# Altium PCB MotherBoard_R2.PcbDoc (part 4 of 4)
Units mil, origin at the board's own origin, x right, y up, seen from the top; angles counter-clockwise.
Board outline 9500 x 4600 mil, 4 copper layers (Top Layer, Power Layer, GND Layer, Bottom Layer), stack 61.6 mil thick; 206 components, 289 nets, 935 pads, 328 vias.
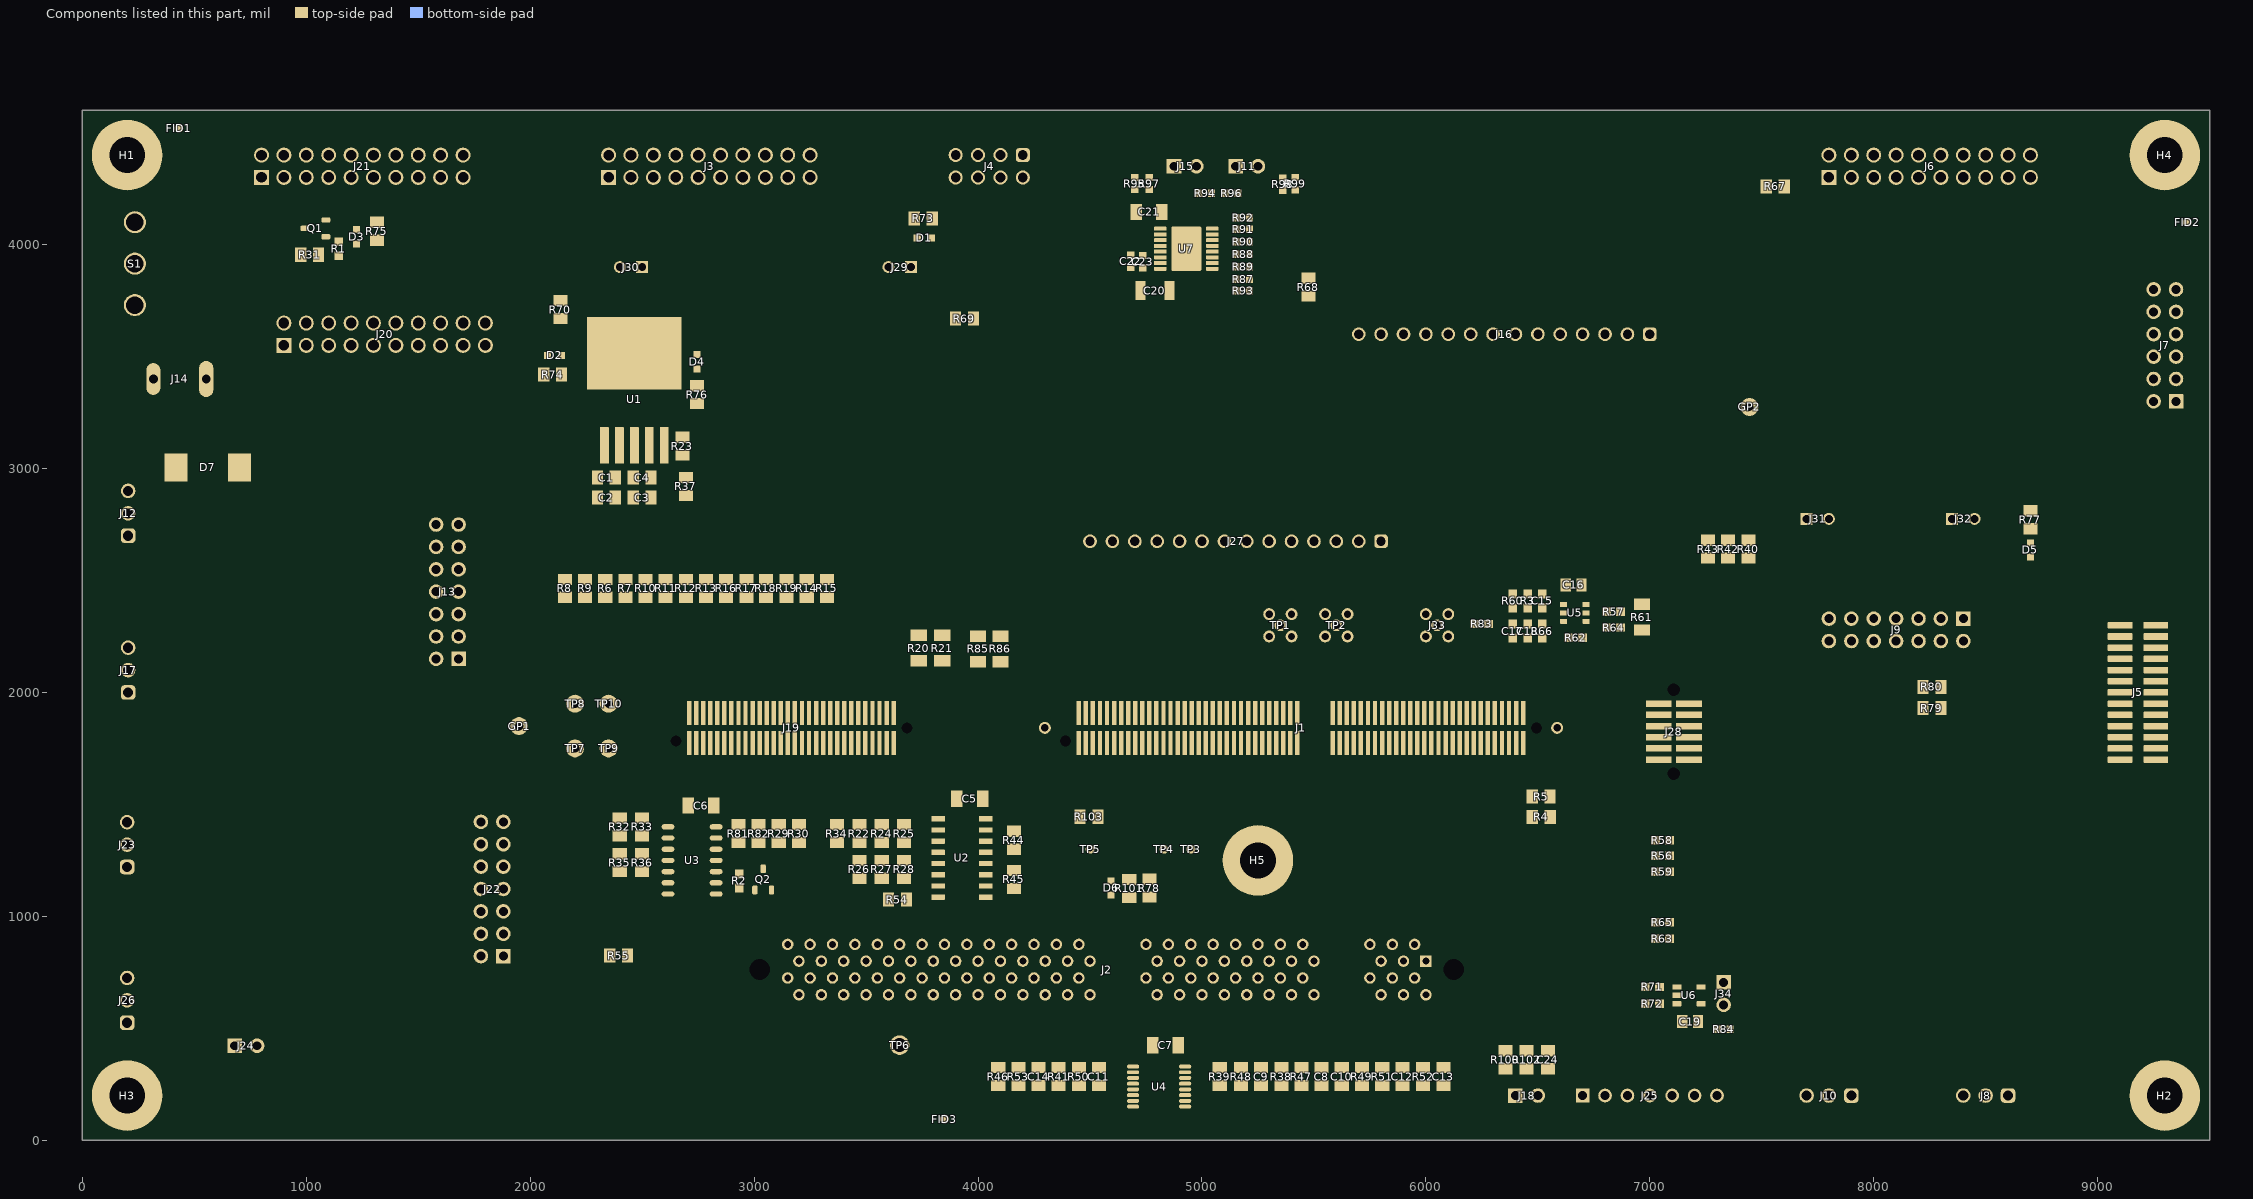
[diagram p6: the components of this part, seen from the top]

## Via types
v1: diameter 28, hole 12, Top Layer to Bottom Layer, 238 vias
v2: diameter 40, hole 20, Top Layer to Bottom Layer, 21 vias
v3: diameter 30, hole 14, Top Layer to Bottom Layer, 19 vias
v4: diameter 28, hole 12, Top Layer to Bottom Layer, tented top, 16 vias
v5: diameter 22, hole 10, Top Layer to Bottom Layer, tented both sides, 12 vias
v6: diameter 60, hole 28, Top Layer to Bottom Layer, 9 vias
v7: diameter 50, hole 28, Top Layer to Bottom Layer, 5 vias
v8: diameter 32, hole 16, Top Layer to Bottom Layer, tented top, 4 vias
v9: diameter 22, hole 10, Top Layer to Bottom Layer, 3 vias
v10: diameter 30, hole 14, Top Layer to Bottom Layer, tented top, 1 vias

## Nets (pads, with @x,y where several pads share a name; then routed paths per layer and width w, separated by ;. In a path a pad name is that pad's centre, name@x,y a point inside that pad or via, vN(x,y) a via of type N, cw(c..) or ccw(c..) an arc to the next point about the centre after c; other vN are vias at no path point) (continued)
pads on no net: FID1.1 FID2.1 FID3.1 H1.1 H4.1 H5.1 J1.32 J1.41 J1.44 J1.66 J1.113 J1.114 J1.115 J1.116 J1.117 J1.181 J1.182 J1.185 J1.186 J2.3 J2.4 J2.5 J2.50 J2.53 J2.54 J2.55 J2.100 J2.MH1 J2.MH2 J3.20 J8.1 J8.2 J8.3 J19.61 J19.62 J19.136 J19.171 J19.172 J19.173 J19.174 J19.175 J19.176 J19.177 J20.8 J20.14 J20.16 J20.18 J21.8 J21.14 J21.16 J21.18 J22.1 J22.3 J28.11 J28.MH1 J28.MH2 S1.1 U7.17@4930,3981.63

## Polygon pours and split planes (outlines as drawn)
VBAT on Power Layer "POWER_LAYER_VBAT_P124" (solid, remove dead copper, pour order 124): 2315.43,3753.33 2733.76,3335 4283.7,3335 4593.7,3645 4635,3686.3 4635,3775 4609.43,3800.57 4134.88,3800.57 4055.18,3720.87 3676.32,3720.87 3635.45,3680 3635.45,3570 3335,3570 3123,3782 2798,3782 2625,3955 2444.67,3774.67 2315.37,3774.67
NetJ14_1 on Power Layer "POWER_LAYER_NETJ14_1_P119" (solid, remove dead copper, pour order 119): 300,3780 300,3680 315,3680 505,3490 604.13,3490 604.13,3594.87 419,3780
GND on Power Layer "POWER_LAYER_GND_P136" (solid, remove dead copper, pour order 136): 2105,4475 2105,4150 2110,4145 2458.43,4145.11 2580.04,4023.49 2580.04,3680 3225,3680 3330,3575 3630,3575 3630,4200 3630,4475
12V on Power Layer "POWER_LAYER_12V_P123" (solid, remove dead copper, pour order 123): 3575,3765 3575,4078.39 3681.61,4185 7210.48,4185 7325,4299.52 7325,4525 7350,4550 8900,4550 9450,4000 9450,3750 9195,3750 9150,3795 9150,4096.92 8746.92,4500 7665.35,4500 7555,4389.65 7555,4200 7175,3820 4125,3820 4040,3735 3604.71,3735
VBAT on Power Layer "POWER_LAYER_VBAT_P121" (solid, remove dead copper, pour order 121): 1425,3789.44 2280.28,3789.44 2315.43,3753.33 2585.56,3750 2625,3789.44 2625,3955 2450,4130 1425,4130
VIN_SMCU on Power Layer "POWER_LAYER_VIN_SMCU_P122" (solid, remove dead copper, pour order 122): 2400,1004.99 2400,545 4615,545 4615,1000.24
VBAT on Power Layer "POWER_LAYER_VBAT_P120" (solid, remove dead copper, pour order 120): 600,50 1390,50 1440,100 1440,4440 1330,4550 600,4550 50,4000 50,600
5V_IPS on Power Layer "POWER_LAYER_5V_IPS_P118" (solid, remove dead copper, pour order 118): 1440,4550 1400,4510 1400,4190 1445,4145 2044.82,4145 2080,4178.98 2080,4300 2250,4470 3380,4470 3650,4200 7200,4200 7300,4300 7300,4525 7275,4550
5V on Power Layer "POWER_LAYER_5V_P125" (solid, remove dead copper, pour order 125): 1450,3785.38 2254.62,3785.37 2725,3315 4296.77,3315 4605.33,3624.1 4660,3676.54 4660,3800 7140,3800 7555,4215 7555,4475 8975,4475 9450,4000 9450,585 8915,50 1500,50 1450,100
GND on GND Layer "GND_LAYER_GND_P117" (solid, remove dead copper, pour order 117): 50,4000 50,600 600,50 8900,50 9450,600 9450,4000 8900,4550 600,4550
no net on Top Layer "TOP_LAYER_NONET_P157" (solid, remove dead copper, pour order 157): 301.94,3780 301.94,3680 330.4,3680 520.4,3490 604.13,3490 604.13,3596.81 420.94,3780
VBAT on Top Layer "TOP_LAYER_VBAT_P155" (solid, remove dead copper, pour order 155): 4190,3675 4143.44,3721.56 4143.44,4143.44 4184,4184 4731.73,4184 4731.73,4115.97 4770,4077.7 4770,3725 4732.57,3675
GND on Top Layer "TOP_LAYER_GND_P153" (solid, remove dead copper, pour order 153): 4874,4071.2 4995,4071.2 4995,4183 4994,4184 4874.56,4184
GND on Top Layer "TOP_LAYER_GND_P151" (solid, remove dead copper, pour order 151): 4870,3752 4993,3752 4993,3890 4994,3891 4882,3891 4882,3824 4870,3812
5V_IPS on Top Layer "TOP_LAYER_5V_IPS_P145" (solid, remove dead copper, pour order 145): 7265,3760 7160,3760 7160,2830 7330,2660 7830,2660 7880,2710 7880,2874.94 7854.94,2900 7785,2900 7760,2875 7760,2731.32 7633.68,2731.32 7565,2800.01 7336.05,2800.01 7265,2871.05
GND on Top Layer "TOP_LAYER_GND_P141" (solid, remove dead copper, pour order 141): 7700,2770 7730,2770 7730,2876.12 7706.12,2900 7397.25,2900 7380,2917.25 7380,3300 7430,3350 7300,3350 7300,2893.25 7372.25,2821 7596.68,2821 7642.68,2775 7700,2775
NetJ14_1 on Top Layer "TOP_LAYER_NETJ14_1_P129" (solid, remove dead copper, pour order 129): 302.25,3780 302.25,3680 330.71,3680 520.71,3490 604.44,3490 604.44,3596.81 421.25,3780
VBAT on Top Layer "TOP_LAYER_VBAT_P140" (solid, remove dead copper, pour order 140): 875.56,3895 830,3849.44 830,2825 1440,2215 1440,3657.97 1572.27,3790.23 2270,3790.23 2310,3750 2584.77,3750 2625,3790.23 2625,3958.37 2453.37,4130 1555,4130 1320,3895
GND on Top Layer "TOP_LAYER_GND_P138" (solid, remove dead copper, pour order 138): 7286,3672.69 7286,3340 9115,3340 9234,3459 9250,3475 9250,3504 9214,3540 7501.33,3540 7333.25,3672.69
5V_IPS on Top Layer "TOP_LAYER_5V_IPS_P139" (solid, remove dead copper, pour order 139): 7160,3760 7160.39,3564 9096,3564 9220,3564 9220,3570 9261,3611 9084,3788 7184.6,3790
EARTH1 on Top Layer "TOP_LAYER_EARTH1_P134" (solid, remove dead copper, pour order 134): 400,50 450,100 450,420 310,560 312.02,562.02 312.02,2897.5 234.52,2975 75,2975 50,2950 50,105 105,50
EARTH on Top Layer "TOP_LAYER_EARTH_P137" (solid, remove dead copper, pour order 137): 7635,240 7660,265 8005,265 8155,115 8742,115 9073,446 9384,446 9450,380 9450,100 9400,50 7685,50 7635,100
VBAT on Top Layer "TOP_LAYER_VBAT_P135" (solid, remove dead copper, pour order 135): 950,4500 900,4550 600,4550 50,4000 50,3020 80,2990 240,2990 330,2900 330,245 525,50 1390,50 1440,100 1440,2250 1150,2540 1150,3400 1150,3770 950,3970
5V_IPS on Top Layer "TOP_LAYER_5V_IPS_P131" (solid, remove dead copper, pour order 131): 1440,4550 1400,4510 1400,4190 1445,4145 2045,4145 2080,4180 2080,4300 2250,4470 3380,4470 3650,4200 7200,4200 7300,4300 7300,4525 7275,4550
3V3 on Top Layer "TOP_LAYER_3V3_P130" (solid, remove dead copper, pour order 130): 2040,3070 1950,2980 1950,2730.02 2000.02,2680 2710,2680 2772.61,2742.61 2772.61,3070
5V_IPS on Bottom Layer "BOTTOM_LAYER_5V_IPS_P127" (solid, remove dead copper, pour order 127): 7063.5,4287.35 7063.5,4180.58 7120.5,4103.37 7120.5,3732.94 7145,3705 7236.42,3705 7250,3718.58 7250,4192.09 7154.75,4287.35
GND on Bottom Layer "BOTTOM_LAYER_GND_P126" (solid, remove dead copper, pour order 126): 7267.85,3708.01 7239.03,3679.84 7239.03,3621.53 7273.48,3588.12 7323.66,3588.12 7395,3659.46 7395,4315.44 7300.44,4410 7185.75,4410 7185.75,4356.33 7267.85,4274.8
GND on Bottom Layer "BOTTOM_LAYER_GND_P133" (solid, remove dead copper, pour order 133): 50,3060 126.8,2983.2 1598.2,2983.2 2080,3465 2080,4065.01 2015.01,4130 1860,4130 1860,4550 600,4550 50,4000
GND on Bottom Layer "BOTTOM_LAYER_GND_P132" (solid, remove dead copper, pour order 132): 1845,4550 1845,4115 2030,4115 2080,4165 2080,4300 2250,4470 3380,4470 3650,4200 7260,4200 7300,4240 7300,4525 7275,4550
3V3 on Bottom Layer "BOTTOM_LAYER_3V3_P128" (solid, remove dead copper, pour order 128): 2255,4450 2100,4295 2100,3460 1450,2810 1450,100 1500,50 8915,50 9450,585 9450,3200 9100,3550 9100,4125 8750,4475 7655,4475 7565,4385 7565,4195 7170,3800 4771.94,3800 4298.42,3320 3615,3320 3560,3375 3560,4120 3632.5,4192.5 3375,4450

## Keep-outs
Keep-Out Layer:
  text ".Layer_Name" at 577,-858.49 h60

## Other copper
Top Layer:
  text ".Layer_Name" at 577,-858.49 h60
GND Layer:
  pour cut-out: 9387.94,3439.94 9413,3465 9413,3565 9388.06,3589.94 9206.38,3589.94 9188,3571.56 9188,3458.33 9206.38,3439.94
  pour cut-out: 9165.82,3647.99 9450,3647.99 9450,3659.28 9170.53,3659.28
  pour cut-out: 9168.06,3653.37
  pour cut-out: 7178.9,3687.01 7275.91,3590 7322.8,3590 7359.14,3626.33 7359.14,3695.86 7244.61,3810.39 7190.39,3810.39 7178.9,3798.9
  pour cut-out: 7650,2850 7625,2825 7625,2725 7650,2700 7850,2700 7875,2725 7875,2825 7850,2850
  pour cut-out: 2061.97,4130 3592.48,4130 3642.48,4180 3641.93,4180.55 3641.93,4190 3630,4190 3585,4145 2061.97,4145
  pour cut-out: 545,3500 565,3500 835,3770 2265,3770 2325,3710 4055,3710 4140,3795 7172.72,3795 7575,4197.28 7575,4385 7650,4460 8775,4460 9050,4185 9050,3793.36 9165.59,3647.45 9170.53,3659.28 9065,3793.02 9065,4190 8780,4475 7639,4475 7555,4391 7555,4209.97 7163.27,3818.24 4123.24,3818.24 4040,3735 2329.31,3735 2271.29,3793.02 828.02,3793.02 545,3510
  pour cut-out: 625,3349.53
  pour cut-out: 895,4115 485,3705 505,3705 900,4100 900,4115
  pour cut-out: 900,4100 2029.37,4100 2100,4165 2100,4294 2256,4450 3372.48,4450 3642.48,4180 7205,4180 7325,4300 7325,4525 7355,4555 7270.01,4555 7299.94,4525 7300,4300 7200,4200 3650.83,4200 3380.83,4470 2250,4470 2080,4300 2080,4180 2015,4115 900,4115
Bottom Layer:
  pour cut-out: 894.99,4114.99 545,3765 545,3500 565,3500 565,3765 900.02,4100.02 2080,4099.98 2080,4115.01
  text ".Layer_Name" at 577,-858.49 h60

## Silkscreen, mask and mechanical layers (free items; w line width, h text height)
Top Overlay:
  lines w10: 29.98,272.3 29.98,1672.3 2029.98,1672.3 2029.98,272.3 375,272.3 ; 500,3150 2200,3150 2200,3800 500,3800 500,3665.04 ; 1925,2720 2875,2720 2875,3675 ; 2100,4500 2100,4200 9100,4200 9100,4500 ; 2155,2550 2165,2550 2200,2585 2205,2585 2240,2550 2250,2550 ; 2512.5,2550 2522.5,2550 2557.5,2585 2562.5,2585 2597.5,2550 2607.5,2550 ; 2872.5,2550 2882.5,2550 2917.5,2585 2922.5,2585 2957.5,2550 2967.5,2550 ; 3232.5,2550 3242.5,2550 3277.5,2585 3282.5,2585 3317.5,2550 3327.5,2550 ; 3390,2680 1925,2680 1925,2200 2985,2200 3400.59,2200 3400.59,2523.07 3402.53,2525 3425,2525 ; 3955,50 3955,565 6150,565 6150,50 ; 4515,3743 4515,4180 ; 5000,195 5000,305 ; 5748.43,3744.03 5748.43,4184.03 ; 6730,800 6730,1085 7335,1085 7335,800 ; 7248.46,4200 7248.97,4200.51 ; 7450,395 6685,395 6685,800 7450,800 ; 8850,1524.7 9050,1525 9050,30 7450,29.7 7450,2529.7 8850,2529.7 8850,1525 ; 9450,1575 8950,1575 8950,4000 9470,4000 ; 29.98,1750 29.98,3150 1830,3150 1829.98,1750 29.98,1750 ; 400,3900 400,4550 2100,4550 2100,3900 400,3900 ; 2100,1675 2100,2165 2105,2170 2490,2170 2490,1675 2100,1675 ; 2225,970 4348.47,970 4348.47,1625 2225,1625 2225,970 ; 2250,3750 3850,3750 3850,4175 2250,4175 2250,3750 ; 3400,2525 3400,3725 7200,3725 7200,2525 3400,2525 ; 6850,1425 6850,2225 7350,2225 7350,1425 6850,1425 ; 7500,2550 8650,2550 8650,2850 7500,2850 7500,2550
  lines w40: 5000,305 5000,310
  text "Fan1" at 4980,4565 h65 r180
  text "Fan2" at 5260,4565 h65 r180
  text "B     R" at 5010,4515 h72.83 r180
  text "B     R" at 5280,4515 h72.83 r180
  text "(5V)" at 5540,4395 h65 r90
  text "(5V)" at 4575,4390 h65 r90
  text "(DRV)" at 5620,4380 h65 r90
  text "(DRV)" at 4655,4375 h65 r90
  text "INVERTER MODULE" at 6010,4342.76 h100
  text "GND /  / 5V (IPS)" at 3575,4265 h72.83
  text "OFF" at 32,4159 h80 r270
  text "INTERMEDIATE" at 1465,4090 h72.83
  text "TRACTION & DC-DC CONTROL MODULE" at 6075,4045 h150
  text "DC-DC GATE DRV POWER SUPPLY" at 2500,4025 h72.83
  text "POWER SUPPLY (IPS)" at 1400,4003.7 h72.83
  text "BLOWER" at 5425,3974.03 h72.83
  text "FAN CTL" at 5435,3929.03 h72.83
  text "VBAT  ->  5V / 5A" at 1490,3925 h60
  text "VBAT  ->  12V" at 2825,3925 h60
  text "'.PRJ_Number'.PCB_Rev" at 6075,3920 h70
  text "VBAT" at 2335,3855 h72.83 r90
  text "GND" at 3690,3790 h72.83
  text "GND" at 2440,3785 h72.83
  text "12V" at 3540,3782 h72.83
  text "ON" at 32,3768 h80 r270
  text "VBAT INPUT" at 620,3602.78 h72.83 r270
  text "READ USER GUIDE BEFORE USE" at 7502,3442.51 h90
  text "CONTROLS POWER SUPPLY" at 1075,3300 h72.83
  text "12V /  / GND /  / 5V_IPS /  / GND /  / 5V /  / GND" at 8965,3240 h65
  text "VBAT  ->  5V / 5A" at 1275,3200 h60
  text "GND" at 7330,3155 h72.83
  text "ANALOG BACK END MODULE" at 4600,3100 h100
  text "POWER SUPPLY" at 1860,3085 h55
  text "5V -> 3V3" at 1865,3010 h60
  text "GND" at 8510.5,2755 h65
  text "GND" at 7515,2750 h65
  text "5V" at 7865,2750 h65
  text "15V" at 8187.5,2750 h65
  text "5V(IPS) ->15V" at 7900,2675 h60
  text "nFLT1H" at 2100,2595 h60
  text "nFLT1L" at 2490,2595 h60
  text "ASCH" at 2855,2595 h60
  text "ASCEN" at 3185,2595 h60
  text "RESOLVER POWER SUPPLY" at 7625,2575 h72.83
  text "nFLT2H" at 2295,2560 h60
  text "nFLT2L" at 2655,2555 h60
  text "ASCL" at 3035,2555 h60
  text "DUAL CAN - 2xTCAN1042" at 302.63,2450 h100
  text "DC-DC CONVERTER  /  / MODULE" at 9181,2354 h90 r90
  text "SEL  SMCU" at 2090,2345 h60 r90
  text "SEL  C2K" at 2010,2340 h60 r90
  text "INV  SAFING" at 1950,2195.02 h65
  text "FAULT CLR" at 4165,2185 h60
  text "DAC-B" at 5245,2150 h72.83
  text "DAC-A" at 5515,2150 h72.83
  text "IDP" at 5986.3,2137.77 h72.83
  text "XBAR TPs" at 2145,2105 h72.83
  text "3V3 SEL" at 8350,2000 h72.83
  text "5V SEL" at 8355,1910 h72.83
  text "SEL  C2K" at 4029,1815 h65 r90
  text "SEL OVP1" at 3807.14,1807.09 h65 r90
  text "SEL OVP2" at 3877.14,1802.09 h65 r90
  text "SEL  SMCU" at 4110,1755 h65 r90
  text "GND" at 1875,1735 h72.83
  text "EXC DAC" at 6124.8,1510 h60
  text "ETAS / EMU" at 6920,1475 h72.83
  text "EXC PWM" at 6120,1425 h60
  text "Io 1" at 6845,1290 h60
  text "DC-DC" at 6650,1240 h60
  text "Io 2" at 6845,1190 h60
  text "VDD" at 4977.8,1155 h60 r90
  text "VDDIO" at 4859.45,1095.5 h60 r90
  text "INVERTER  SAFING" at 2301.77,1055 h60 r90
  text "ERRSTS" at 4535,1055 h60 r90
  text "ASC: DEF / SMCU" at 4330,997.43 h60 r90
  text "ASC: ENDRV" at 3390,986.5 h60
  text "RESOLVER" at 7925,954.7 h100
  text "PWM 6B" at 6758.29,950 h60
  text "TCAN4550" at 779.98,922.3 h100
  text "PWM F" at 7135,915 h60
  text "PWM 7A" at 6758.29,877.96 h60
  text "VBAT TO SMCU" at 2185,730 h55
  text "C2K EN" at 6750,665 h60
  text "SMCU EN" at 6700,585 h60
  text "VOLTAGE MONITOR" at 4500,505 h70
  text "DC DC SAFING" at 6715,418.83 h60
  text "EARTH" at 9188,399 h72.83
  text "ENDRV" at 3555.39,278.39 h60
  text "VREF" at 5420,200 h70 r270
  text "3V3" at 4150,190 h70 r270
  text "15V" at 6011.5,190 h70 r270
  text "VDD" at 4975,185 h70 r270
  text "12V" at 5645,185 h70 r270
  text "5V_I" at 5835.87,185 h70 r270
  text "5V" at 4425,180 h70 r270
  text "VIO" at 5150,180 h70 r270
  text "EARTH" at 366,77 h72.83
  text "Fan Cntl Pot" at 6335,25 h50
  text "QEP / SPI PORT (TEST ONLY)" at 6695.43,25 h50
  text ".Layer_Name" at 577,-858.49 h60
Bottom Overlay:
  text ".Layer_Name" at 577,-858.49 h60
Top Paste:
  text ".Layer_Name" at 577,-858.49 h60
Bottom Paste:
  text ".Layer_Name" at 577,-858.49 h60
Top Solder:
  text ".Layer_Name" at 577,-858.49 h60
  text ".Layer_Name" at 577,-858.49 h60
Bottom Solder:
  text ".Layer_Name" at 577,-858.49 h60
Drill Guide:
  text ".Layer_Name" at 577,-858.49 h60
M1 Board Outline:
  the board outline again, w10
  text ".Layer_Name" at 577,-858.49 h60
M2 Board Dimensions:
  rectangle: 0,-275 125,-150
  rectangle: 125,-400 500,-275
  lines w7: 0,-275 1000,-275 ; 125,-400 125,-150 ; 250,-400 250,-150 ; 500,-400 500,-150 ; 750,-400 750,-150 ; 0,-400 1000,-400 1000,-150 0,-150 0,-400
  text ".Layer_Name" at 577,-858.49 h60
M3 3D STEP Top:
  text ".Layer_Name" at 577,-858.49 h60
M4 3D STEP Bottom:
  text ".Layer_Name" at 577,-858.49 h60
M5 Assembly Top:
  lines w10: -292,-930.17 6308,-930.17 ; -292,-726.83 6310,-726.83 ; -292,-523.5 -292,-1133.5 3713,-1133.5 6310,-1133.5 6310,-523.5 -291.5,-523.5 -291.5,-1133.5 1284,-1133.5 ; 2173,-1133.5 2173,-523.5 ; 3440,-726.83 3440,-523.5 ; 4280,-726.83 4280,-523.5 ; 4902,-1140 4902,-937.17
  text "COMPONENTS MARKED 'DNP' SHOULD NOT BE POPULATED." at 1153.5,-318.5 h60
  text "ASSEMBLY VARIANT:" at 1153,-434 h60
  text ".VariantName" at 2189,-434 h60
  text "PCB VIEWED FROM TOP SIDE" at -228.5,-655.67 h60
  text "BOARD #:" at 2248,-655.67 h60
  text ".PRJ_Number" at 2793.5,-655.67 h60
  text "REV:" at 3638,-655.67 h60
  text ".PCB_Rev" at 3929.5,-655.67 h60
  text "SVN REV:" at 4476,-655.67 h60
  text ".VersionControl_RevNumber" at 4982,-655.67 h60
  text "TID #:" at 2248,-859 h60
  text ".TID" at 2793.5,-859 h60
  text "PLOT NAME =" at -228.5,-1064.34 h60
  text ".plot_File_Name" at 577,-1064.34 h60
  text "GENERATED    :" at 2250,-1064.34 h60
  text ".Print_Date" at 3119.5,-1064.34 h60
  text ".Print_Time" at 3848.5,-1064.34 h60
  text "TEXAS INSTRUMENTS" at 5113,-1064.34 h60
M6 Assembly Bottom:
  lines w10: -292.5,-727.33 6309.5,-727.33 ; -290.5,-930.67 6309.5,-930.67 ; 1115.5,-1140.5 1115.5,-937.67 ; 1737.5,-727.33 1737.5,-524 ; 2577.5,-727.33 2577.5,-524 ; 3844.5,-1134 3844.5,-524 ; 4733.5,-1134 6309,-1134 6309,-524 -292.5,-524 -292.5,-1134 2304.5,-1134 6309.5,-1134 6309.5,-524
  text "COMPONENTS MARKED 'DNP' SHOULD NOT BE POPULATED." at 6102,-318 h60
  text ".VariantName" at 5058,-434 h60
  text "ASSEMBLY VARIANT:" at 6097,-434 h60
  text ".VersionControl_RevNumber" at 1035.5,-656.17 h60
  text "SVN REV:" at 1541.5,-656.17 h60
  text ".PCB_Rev" at 2088,-656.17 h60
  text "REV:" at 2379.5,-656.17 h60
  text ".PRJ_Number" at 3224,-656.17 h60
  text "BOARD #:" at 3769.5,-656.17 h60
  text "PCB VIEWED FROM BOTTOM SIDE" at 6246,-656.17 h60
  text ".TID" at 3224,-859.5 h60
  text "TID #:" at 3769.5,-859.5 h60
  text "TEXAS INSTRUMENTS" at 904.5,-1064.84 h60
  text ".Print_Time" at 2169,-1064.84 h60
  text ".Print_Date" at 2898,-1064.84 h60
  text "GENERATED    :" at 3767.5,-1064.84 h60
  text ".plot_File_Name" at 5440.5,-1064.84 h60
  text "PLOT NAME =" at 6246,-1064.84 h60
M9 Title Sheet:
  drawing of 57 lines, arcs and shapes, not listed
  text "1" at 739.84,8036.5 h70
  text "2" at 3235.5,8036.5 h70
  text "3" at 5724.84,8036.5 h70
  text "4" at 8231.51,8036.5 h70
  text "5" at 10730.5,8036.5 h70
  text "6" at 13235.5,8036.5 h70
  text "A" at -416.5,6893.5 h70
  text "A" at 14383.5,6893.5 h70
  text "B" at -416.5,4513.5 h70
  text "B" at 14383.5,4513.5 h70
  text "C" at -416.5,2138.5 h70
  text "C" at 14383.5,2138.5 h70
  text "PROJECT TITLE:" at 11343.5,277.5 h45
  text ".PRJ_Title" at 11393.5,144.17 h70
  text "DESIGNED FOR:" at 11343.5,-23.5 h45
  text ".PRJ_Customer" at 11393.5,-163.5 h70
  text "D" at -416.5,-231.5 h70
  text "D" at 14383.5,-231.5 h70
  text "FILE NAME:" at 11343.5,-323.5 h45
  text ".PCB_File_Name_No_Path" at 11393.5,-443.5 h70
  text "Texas Instruments (TI) and/or its licensors do not warrant the accuracy or completeness of this specification" at 6374,-605.34 h45
  text "ENGINEER:" at 11343.5,-613.5 h45
  text "LAYOUT BY:" at 12848.5,-613.5 h45
  text "or any information contained therein. TI and/or its licensors do not warrant that this design will meet" at 6329.01,-718 h45
  text ".PRJ_Engineer" at 11393.5,-768.49 h70
  text ".PCB_Layout" at 12899,-768.49 h70
  text "the specifications, will be suitable for your application or fit for any particular purpose, or will operate in" at 6329.01,-830.67 h45
  text ".Layer_Name" at 577,-858.49 h60
  text "ALTIUM DESIGNER VERSION:" at 12848.5,-923.5 h45
  text "an implementation. TI and/or its licensors do not warrant that the design is production worthy. You should" at 6329.01,-943.33 h45
  text "completely validate and test your design implementation to confirm the system functionality for your application." at 6374,-1056 h45
  text ".print_Scale" at 11393.5,-1056.83 h70
  text ".Application_BuildNumber" at 12899,-1056.83 h70
  text "1" at 739.84,-1263.5 h70
  text "2" at 3235.5,-1263.5 h70
  text "3" at 5724.84,-1263.5 h70
  text "4" at 8231.51,-1263.5 h70
  text "5" at 10730.5,-1263.5 h70
  text "6" at 13235.5,-1263.5 h70
M10 Fab Notes:
  drawing of 189 lines, arcs and shapes, not listed
  text "DESIGN INFORMATION" at 12382.02,6356.17 h60
  text "MIN. TRACK WIDTH:" at 11737.46,6224.05 h60
  text "8" at 12833.7,6224.05 h60
  text "MIL" at 12988.46,6224.05 h60
  text "MIN. CLEARANCE:" at 11737.46,6099.92 h60
  text "0.2" at 12773.7,6099.93 h60
  text "mm" at 12988.46,6099.92 h60
  text "MIN. VIA PAD SIZE:" at 11737.46,5975.8 h60
  text "24" at 12803.71,5975.8 h60
  text "MIL" at 12988.46,5975.8 h60
  text "0.05mm (2MIL)" at 12432.46,5845.9 h60
  text "MINIMUM ANNULAR RING" at 11408.23,5837.67 h60
  text "EXTERNAL" at 13140.46,5837.67 h60
  text "PER" at 11608.23,5727.55 h60
  text "IPC-D-275 CLASS 2 LEVEL C" at 11828.23,5727.54 h60
  text "MIL, HOLES" at 13316.46,5627.07 h60
  text "+/-" at 12924,5618.48 h60
  text "+/-" at 13778,5618.48 h60
  text "REGISTRATION TOLERANCES:" at 11408.23,5617.42 h60
  text "METAL" at 12608,5617.42 h60
  text "5" at 13184.2,5617.42 h60
  text "3" at 14017.2,5617.42 h60
  text "MIL" at 14133.46,5617.42 h60
  text "HOLE SIZE TOLERANCE (UNLESS OTHERWISE SPECIFIED):" at 11408.23,5519.1 h60
  text "+/-" at 13778,5516.23 h60
  text "3" at 14017.2,5515.17 h60
  text "MIL" at 14133.46,5515.17 h60
  text "MATERIAL:" at 11333.46,5377.52 h60
  text "FR-4 High Tg" at 12319.9,5249 h60
  text "X" at 12175.46,5241.01 h60
  text "FR-408" at 11754.46,5236.49 h60
  text "OTHER" at 13242.46,5236.49 h60
  text "62 MIL (1.6mm) +/-10%" at 12074.56,5093.46 h60
  text "X" at 11954.46,5091.01 h60
  text "THICKNESS:" at 11408.23,5085.24 h60
  text "OTHER" at 13359.46,5085.24 h60
  text "TOLERANCE:" at 11408.23,4946.92 h60
  text "X" at 12256.46,4946.92 h60
  text "ANSI IPC-6012 TYPE 3 CLASS 2" at 12434.48,4946.92 h60
  text "OTHER +/-" at 12434.46,4802.73 h60
  text "BOW & TWIST:" at 11408.23,4657.54 h60
  text "X" at 12256.46,4657.54 h60
  text "ANSI IPC-6012 TYPE 3 CLASS 2" at 12434.48,4657.54 h60
  text "OTHER +/-" at 12434.46,4510.85 h60
  text "DRILLING:" at 11333.46,4380.23 h60
  text "NC_DRILL FILES" at 13094.46,4275.04 h60
  text "REFERENCE:" at 11408.23,4271.1 h60
  text "X" at 12065.46,4271.01 h60
  text "AS SHOWN" at 12243.46,4271.1 h60
  text "X" at 12966.46,4271.1 h60
  text "OTHER" at 13392.46,4128.85 h60
  text "PTH COPPER THICKNESS:" at 11407.91,4125.32 h60
  text "X" at 12547.14,4125.32 h60
  text "20-30 um" at 12675.14,4125.32 h60
  text "BOARD FINISH:" at 11333.46,3977.73 h60
  text "SILKSCREEN:" at 11488.68,3867.6 h60
  text "X" at 12446.46,3867.6 h60
  text "TOP" at 12563.46,3867.6 h60
  text "X" at 12956.46,3867.6 h60
  text "BOTTOM" at 13074.46,3867.6 h60
  text "SILKSCREEN COLOR:" at 11488.68,3712.41 h60
  text "X" at 12445.46,3712.41 h60
  text "WHITE" at 12563.46,3712.41 h60
  text "OTHER" at 13074.46,3712.41 h60
  text "X" at 12576.46,3568.96 h60
  text "GREEN" at 12694.46,3568.96 h60
  text "OTHER" at 13312.46,3568.96 h60
  text "SOLDER RESIST COLOR:" at 11488.68,3562.1 h60
  text "X" at 12576.46,3414.71 h60
  text "MATTE" at 12694.46,3414.71 h60
  text "SEMI-GLOSS" at 13312,3414.07 h60
  text "IMMERSION GOLD (ENIG)" at 12394.46,3241.94 h60
  text "ENEPIG" at 13732,3234.72 h60
  text "SURFACE FINISH:" at 11333.46,3233.72 h60
  text "HASL LEAD FREE" at 13443.44,3101.4 h60
  text "X" at 12930,3100 h60
  text "IMM. TIN/SILVER OR EQUIV" at 11663,3096.4 h60
  text "OTHER" at 13094.46,3092.47 h60
  text "ARRAY/PANEL:" at 11333.46,2937.09 h60
  text "CUT AND TRIM PER M1 BOARD OUTLINE" at 12394.46,2928.87 h60
  text "N.C. ROUTE" at 12394.46,2792.9 h60
  text "X" at 13082.46,2792.9 h60
  text "V. SCORE" at 13260.46,2792.9 h60
  text "CERTIFICATION:" at 11333.46,2663.77 h60
  text "MATERIALS AND WORKMANSHIP FOR ALL PCBS" at 12058.46,2663.77 h60
  text "TO MEET OR EXCEED THE REQUIREMENTS OF:" at 12058.46,2569.71 h60
  text "X" at 11695.97,2441.08 h60
  text "ANSI IPC-A-600F CLASS ->" at 11823.96,2441.08 h60
  text "X" at 13471.97,2441.08 h60
  text "2" at 13581.96,2441.08 h60
  text "1" at 13266.96,2439.58 h60
  text "3" at 13935.96,2439.58 h60
  text "X" at 12507.97,2293.39 h60
  text "RoHS" at 12635.96,2293.39 h60
  text "OTHER" at 13280.36,2293.39 h60
  text "PER ORDER" at 13677.42,2293.39 h60
  text "ALL BOARDS MUST MEET OR EXCEED UL94-V0 REQUIREMENTS." at 11361,2139.57 h60
  text "PCB MUST BEAR THE UL94V-0 UL REGISTERED MATERIAL ID NUMBER" at 11361,2023.5 h60
  text "ADDITIONAL REQUIREMENTS:" at 11333.46,1854.08 h60
  text "MICROSECTION:" at 11408.23,1746.95 h60
  text "YES" at 12313.96,1746.95 h60
  text "REQUIRED" at 13175.46,1602.62 h60
  text "BARE BOARD ELEC. TEST:" at 11408.23,1599.76 h60
  text "NONE" at 12713.96,1599.76 h60
  text "X" at 13057.46,1599.76 h60
  text "PER ORDER" at 13767.46,1599.76 h60
  text "XX MIL VIAS REQUIRE NON-CONDUCTIVE FILL AND PLANARIZE" at 11576.38,1394.82 h59
  text "XX MIL VIAS REQUIRE CONDUCTIVE FILL AND PLANARIZE" at 11584.38,1290.84 h60
  text "OUTER XX MIL TRACES REQUIRE 50 OHM SINGLE-ENDED IMPEDANCE" at 11583.39,1127.46 h58
  text "LAYER 2 & 3 (INNER LAYERS) XX MIL WIDE, XX MIL SPACE / TRACES REQUIRE 100 OHM DIFFERENTIAL IMPEDANCE" at 11575.39,891.74 h60
  text ".Layer_Name" at 577,-858.49 h60
M11 Gerber Information:
  lines w10: -292,-930.17 6308,-930.17 ; -292,-726.83 6310,-726.83 ; -292,-523.5 -292,-1133.5 3713,-1133.5 6310,-1133.5 6310,-523.5 -291.5,-523.5 -291.5,-1133.5 1284,-1133.5 ; 2173,-1133.5 2173,-523.5 ; 3440,-726.83 3440,-523.5 ; 4280,-726.83 4280,-523.5 ; 4902,-1140 4902,-937.17
  text "ALL ARTWORK VIEWED FROM TOP SIDE" at -228.5,-655.67 h60
  text "BOARD #:" at 2248,-655.67 h60
  text ".PRJ_Number" at 2793.5,-655.67 h60
  text "REV:" at 3638,-655.67 h60
  text ".PCB_Rev" at 3929.5,-655.67 h60
  text "SVN REV:" at 4476,-655.67 h60
  text ".VersionControl_RevNumber" at 4982,-655.67 h60
  text "LAYER NAME =" at -228.5,-858.49 h60
  text "TID #:" at 2248,-859 h60
  text ".TID" at 2793.5,-859 h60
  text "PLOT NAME =" at -228.5,-1064.34 h60
  text ".plot_File_Name" at 577,-1064.34 h60
  text "GENERATED    :" at 2250,-1064.34 h60
  text ".Print_Date" at 3119.5,-1064.34 h60
  text ".Print_Time" at 3848.5,-1064.34 h60
  text "TEXAS INSTRUMENTS" at 5113,-1064.34 h60
M12 Stackup:
  drawing of 295 lines, arcs and shapes, not listed
  text "Layer" at 620.88,6515 h60
  text "Name" at 1030.79,6515 h60
  text "Material" at 1960.54,6515 h60
  text "Thickness" at 2820.3,6515 h60
  text "Constant" at 3470.14,6515 h60
  text "Board Layer Stack" at 4040,6515 h60
  text "1" at 620.88,6395 h60
  text "Top Overlay" at 1030.79,6395 h60
  text "2" at 620.88,6275 h60
  text "Top Solder" at 1030.79,6275 h60
  text "Solder Resist" at 1960.54,6275 h60
  text "0.40mil" at 2820.3,6275 h60
  text "3.5" at 3470.14,6275 h60
  text "3" at 620.88,6155 h60
  text "Top Layer" at 1030.79,6155 h60
  text "Copper" at 1960.54,6155 h60
  text "1.40mil" at 2820.3,6155 h60
  text "4" at 620.88,6035 h60
  text "Dielectric 1" at 1030.79,6035 h60
  text "FR-4" at 1960.54,6035 h60
  text "8.00mil" at 2820.3,6035 h60
  text "4.2" at 3470.14,6035 h60
  text "5" at 620.88,5915 h60
  text "Power Layer" at 1030.79,5915 h60
  text "Copper" at 1960.54,5915 h60
  text "1.40mil" at 2820.3,5915 h60
  text "6" at 620.88,5795 h60
  text "Dielectric 2" at 1030.79,5795 h60
  text "FR-4" at 1960.54,5795 h60
  text "40.00mil" at 2820.3,5795 h60
  text "4.2" at 3470.14,5795 h60
  text "7" at 620.88,5675 h60
  text "GND Layer" at 1030.79,5675 h60
  text "Copper" at 1960.54,5675 h60
  text "1.40mil" at 2820.3,5675 h60
  text "8" at 620.88,5555 h60
  text "Dielectric 3" at 1030.79,5555 h60
  text "FR-4" at 1960.54,5555 h60
  text "8.00mil" at 2820.3,5555 h60
  text "4.2" at 3470.14,5555 h60
  text "9" at 620.88,5435 h60
  text "Bottom Layer" at 1030.79,5435 h60
  text "Copper" at 1960.54,5435 h60
  text "1.40mil" at 2820.3,5435 h60
  text "10" at 620.88,5315 h60
  text "Bottom Solder" at 1030.79,5315 h60
  text "Solder Resist" at 1960.54,5315 h60
  text "0.40mil" at 2820.3,5315 h60
  text "3.5" at 3470.14,5315 h60
  text "11" at 620.88,5195 h60
  text "Bottom Overlay" at 1030.79,5195 h60
  text ".Layer_Name" at 577,-858.49 h60
M13 Component Bodies Top:
  text ".Layer_Name" at 577,-858.49 h60
M14 Component Bodies Bottom:
  text ".Layer_Name" at 577,-858.49 h60
M15 Courtyards Top:
  text ".Layer_Name" at 577,-858.49 h60
M16 Courtyards Bottom:
  text ".Layer_Name" at 577,-858.49 h60
Drill Drawing:
  drawing of 184 lines, arcs and shapes, not listed
  text "Symbol" at 7090.87,11788.02 h72
  text "Quantity" at 7391.44,11788.02 h72
  text "Finished Hole Size" at 7723.44,11788.02 h72
  text "Plated" at 8360,11788.02 h72
  text "Hole Type" at 8619.14,11788.02 h72
  text "Drill Layer Pair" at 8994.3,11788.02 h72
  text "Hole Tolerance" at 9718.63,11788.02 h72
  text "4" at 7391.44,11663.7 h60
  text "50.00mil (1.270mm)" at 7723.44,11663.7 h60
  text "NPTH" at 8360,11663.7 h60
  text "Round" at 8619.14,11663.7 h60
  text "Top Layer - Bottom Layer" at 8994.3,11663.7 h60
  text "2" at 7391.44,11539.38 h60
  text "55.91mil (1.420mm)" at 7723.44,11539.38 h60
  text "NPTH" at 8360,11539.38 h60
  text "Round" at 8619.14,11539.38 h60
  text "Top Layer - Bottom Layer" at 8994.3,11539.38 h60
  text "2" at 7391.44,11415.06 h60
  text "92.91mil (2.360mm)" at 7723.44,11415.06 h60
  text "NPTH" at 8360,11415.06 h60
  text "Round" at 8619.14,11415.06 h60
  text "Top Layer - Bottom Layer" at 8994.3,11415.06 h60
  text "15" at 7391.44,11290.74 h60
  text "10.00mil (0.254mm)" at 7723.44,11290.74 h60
  text "PTH" at 8360,11290.74 h60
  text "Round" at 8619.14,11290.74 h60
  text "Top Layer - Bottom Layer" at 8994.3,11290.74 h60
  text "K" at 7065.58,11280.75 h55.25
  text "254" at 7391.44,11166.42 h60
  text "12.00mil (0.305mm)" at 7723.44,11166.42 h60
  text "PTH" at 8360,11166.42 h60
  text "Round" at 8619.14,11166.42 h60
  text "Top Layer - Bottom Layer" at 8994.3,11166.42 h60
  text "B" at 7065.58,11156.43 h55.25
  text "20" at 7391.44,11042.1 h60
  text "14.00mil (0.356mm)" at 7723.44,11042.1 h60
  text "PTH" at 8360,11042.1 h60
  text "Round" at 8619.14,11042.1 h60
  text "Top Layer - Bottom Layer" at 8994.3,11042.1 h60
  text "F" at 7065.58,11032.11 h55.25
  text "4" at 7391.44,10917.78 h60
  text "16.00mil (0.406mm)" at 7723.44,10917.78 h60
  text "PTH" at 8360,10917.78 h60
  text "Round" at 8619.14,10917.78 h60
  text "Top Layer - Bottom Layer" at 8994.3,10917.78 h60
  text "G" at 7065.58,10907.79 h55.25
  text "24" at 7391.44,10793.46 h60
  text "20.00mil (0.508mm)" at 7723.44,10793.46 h60
  text "PTH" at 8360,10793.46 h60
  text "Round" at 8619.14,10793.46 h60
  text "Top Layer - Bottom Layer" at 8994.3,10793.46 h60
  text "C" at 7065.58,10783.47 h55.25
  text "14" at 7391.44,10669.14 h60
  text "28.00mil (0.711mm)" at 7723.44,10669.14 h60
  text "PTH" at 8360,10669.14 h60
  text "Round" at 8619.14,10669.14 h60
  text "Top Layer - Bottom Layer" at 8994.3,10669.14 h60
  text "D" at 7065.58,10659.15 h55.25
  text "100" at 7391.44,10544.82 h60
  text "31.00mil (0.787mm)" at 7723.44,10544.82 h60
  text "PTH" at 8360,10544.82 h60
  text "Round" at 8619.14,10544.82 h60
  text "Top Layer - Bottom Layer" at 8994.3,10544.82 h60
  text "2" at 7391.44,10420.5 h60
  text "33.07mil (0.840mm)" at 7723.44,10420.5 h60
  text "PTH" at 8360,10420.5 h60
  text "Round" at 8619.14,10420.5 h60
  text "Top Layer - Bottom Layer" at 8994.3,10420.5 h60
  text "15" at 7391.44,10296.18 h60
  text "33.07mil (0.840mm)" at 7723.44,10296.18 h60
  text "PTH" at 8360,10296.18 h60
  text "Round" at 8619.14,10296.18 h60
  text "Top Layer - Bottom Layer" at 8994.3,10296.18 h60
  text "J" at 7065.58,10286.19 h55.25
  text "8" at 7391.44,10171.86 h60
  text "35.04mil (0.890mm)" at 7723.44,10171.86 h60
  text "PTH" at 8360,10171.86 h60
  text "Round" at 8619.14,10171.86 h60
  text "Top Layer - Bottom Layer" at 8994.3,10171.86 h60
  text "6" at 7391.44,10047.54 h60
  text "37.99mil (0.965mm)" at 7723.44,10047.54 h60
  text "PTH" at 8360,10047.54 h60
  text "Round" at 8619.14,10047.54 h60
  text "Top Layer - Bottom Layer" at 8994.3,10047.54 h60
  text "A" at 7065.58,10037.55 h55.25
  text "64" at 7391.44,9923.22 h60
  text "40.00mil (1.016mm)" at 7723.44,9923.22 h60
  text "PTH" at 8360,9923.22 h60
  text "Round" at 8619.14,9923.22 h60
  text "Top Layer - Bottom Layer" at 8994.3,9923.22 h60
  text "7" at 7391.44,9798.9 h60
  text "40.16mil (1.020mm)" at 7723.44,9798.9 h60
  text "PTH" at 8360,9798.9 h60
  text "Round" at 8619.14,9798.9 h60
  text "Top Layer - Bottom Layer" at 8994.3,9798.9 h60
  text "28" at 7391.44,9674.58 h60
  text "40.95mil (1.040mm)" at 7723.44,9674.58 h60
  text "PTH" at 8360,9674.58 h60
  text "Round" at 8619.14,9674.58 h60
  text "Top Layer - Bottom Layer" at 8994.3,9674.58 h60
  text "8" at 7391.44,9550.26 h60
  text "43.31mil (1.100mm)" at 7723.44,9550.26 h60
  text "PTH" at 8360,9550.26 h60
  text "Round" at 8619.14,9550.26 h60
  text "Top Layer - Bottom Layer" at 8994.3,9550.26 h60
  text "18" at 7391.44,9425.94 h60
  text "45.28mil (1.150mm)" at 7723.44,9425.94 h60
  text "PTH" at 8360,9425.94 h60
  text "Round" at 8619.14,9425.94 h60
  text "Top Layer - Bottom Layer" at 8994.3,9425.94 h60
  text "80" at 7391.44,9301.62 h60
  text "47.24mil (1.200mm)" at 7723.44,9301.62 h60
  text "PTH" at 8360,9301.62 h60
  text "Round" at 8619.14,9301.62 h60
  text "Top Layer - Bottom Layer" at 8994.3,9301.62 h60
  text "1" at 7391.44,9177.3 h60
  text "63.00mil (1.600mm)" at 7723.44,9177.3 h60
  text "PTH" at 8360,9177.3 h60
  text "Round" at 8619.14,9177.3 h60
  text "Top Layer - Bottom Layer" at 8994.3,9177.3 h60
  text "3" at 7391.44,9052.98 h60
  text "78.74mil (2.000mm)" at 7723.44,9052.98 h60
  text "PTH" at 8360,9052.98 h60
  text "Round" at 8619.14,9052.98 h60
  text "Top Layer - Bottom Layer" at 8994.3,9052.98 h60
  text "5" at 7391.44,8928.66 h60
  text "160.00mil (4.064mm)" at 7723.44,8928.66 h60
  text "PTH" at 8360,8928.66 h60
  text "Round" at 8619.14,8928.66 h60
  text "Top Layer - Bottom Layer" at 8994.3,8928.66 h60
  text "E" at 7065.58,8918.67 h55.25
  text "1" at 7391.44,8804.34 h60
  text "39.37mil (1.000mm)" at 7723.44,8804.34 h60
  text "PTH" at 8360,8804.34 h60
  text "Slot" at 8619.14,8804.34 h60
  text "Top Layer - Bottom Layer" at 8994.3,8804.34 h60
  text "H" at 7065.58,8794.35 h55.25
  text "1" at 7391.44,8680.02 h60
  text "39.37mil (1.000mm)" at 7723.44,8680.02 h60
  text "PTH" at 8360,8680.02 h60
  text "Slot" at 8619.14,8680.02 h60
  text "Top Layer - Bottom Layer" at 8994.3,8680.02 h60
  text "686 Total" at 7391.44,8555.7 h60
  text "Slot definitions :" at 7090.87,8468.68 h60
  text "Routed Path Length" at 7541.59,8468.68 h60
  text "= Calculated from tool start centre position to tool end centre position." at 8081.32,8468.68 h60
  text "Hole Length" at 7541.59,8418.95 h60
  text "= Routed Path Length + Tool Size = Slot length as defined in the PCB layout" at 7881.52,8418.95 h60
  text ".Layer_Name" at 577,-858.49 h60
Mechanical 17:
  text ".Layer_Name" at 577,-858.49 h60
Mechanical 18:
  text ".Layer_Name" at 577,-858.49 h60
Mechanical 19:
  text ".Layer_Name" at 577,-858.49 h60

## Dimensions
0,-400 to 1000,-400 on M2 Board Dimensions
0,0 to 0,4600 on M2 Board Dimensions
0,0 to 9500,0 on M2 Board Dimensions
